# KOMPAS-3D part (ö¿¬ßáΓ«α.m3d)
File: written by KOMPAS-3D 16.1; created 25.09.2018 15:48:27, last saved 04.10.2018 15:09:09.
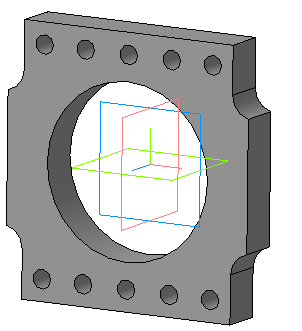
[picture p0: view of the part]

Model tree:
1. Эскиз:1
2. Операция выдавливания:1
     Расстояние 1 = 20
3. Скругление:1
     Радиус = 10
4. Эскиз:2
5. Вырезать элемент выдавливания:1
     Расстояние 1 = 20
6. Массив по сетке:1  (with: Вырезать элемент выдавливания:1, Эскиз:2)  (4 pattern instances)
     Угол раствора = -90; Шаг 2 = -2.15642; Номер 1 = 1
7. Эскиз:3
8. Вырезать элемент выдавливания:2
     Расстояние 1 = 20
9. Массив по сетке:2  (with: Вырезать элемент выдавливания:2, Эскиз:3)  (labels: А302-01.05.012)  (6 pattern instances)
     Угол раствора = -90; Номер 1 = 1

Expressions: v64*2; v81*2; v174*2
